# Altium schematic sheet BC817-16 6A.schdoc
size 127 x 101 mm
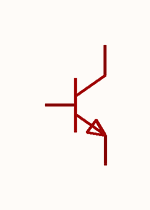
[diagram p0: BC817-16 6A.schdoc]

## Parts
Q?  bc817(range:100-250)  [SOT-23-3_L2.9-W1.3-P1.90-LS2.4-BR]  (value not drawn)

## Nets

Not connected (* = marked no-connect by the designer): Q? 1(B) 2(E) 3(C)

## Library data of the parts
Q? = bc817(range:100-250): 晶体管类型:NPN;集电极电流(Ic):500mA;集射极击穿电压(Vceo):45V;耗散功率(Pd):300mW;直流电流增益(hFE):100;; Manufacturer: CJ(江苏长电/长晶); Symbol: BC817-16 6A; AddInBom: yes; ModelId: c62791f0466c4ae2a892c056b845b0ca; ModelName: SOT-23-3P_L2.9-W1.3-H1.0-LS2.4-P0.95; ModelTransform: 98.425,114.173,0,180,0,0,0.0005,-0.0005,0; type: NPN; Current - Collector(Ic): 500mA; Collector - Emitter Voltage VCEO: 45V; Pd - Power Dissipation: 300mW; DC Current Gain: 100; Transition frequency(fT): 100MHz; Current - Collector Cutoff: 100nA; Vce Saturation(VCE(sat)): 700mV; Emitter-Base Voltage(Vebo): 5V; Number: 1个NPN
